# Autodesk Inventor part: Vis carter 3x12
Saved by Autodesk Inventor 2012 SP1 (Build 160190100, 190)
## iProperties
Created: 2014-12
Part Number: Vis carter 3x12
Material: Default
Document SubType Name: Modeling
Designer: Bruno
Density: 1 g/cm^3
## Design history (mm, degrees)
node "Vis carter 3x121"
node "Vis carter 3x12"
node "Base1"
